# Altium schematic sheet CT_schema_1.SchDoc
size 542 x 258 mm
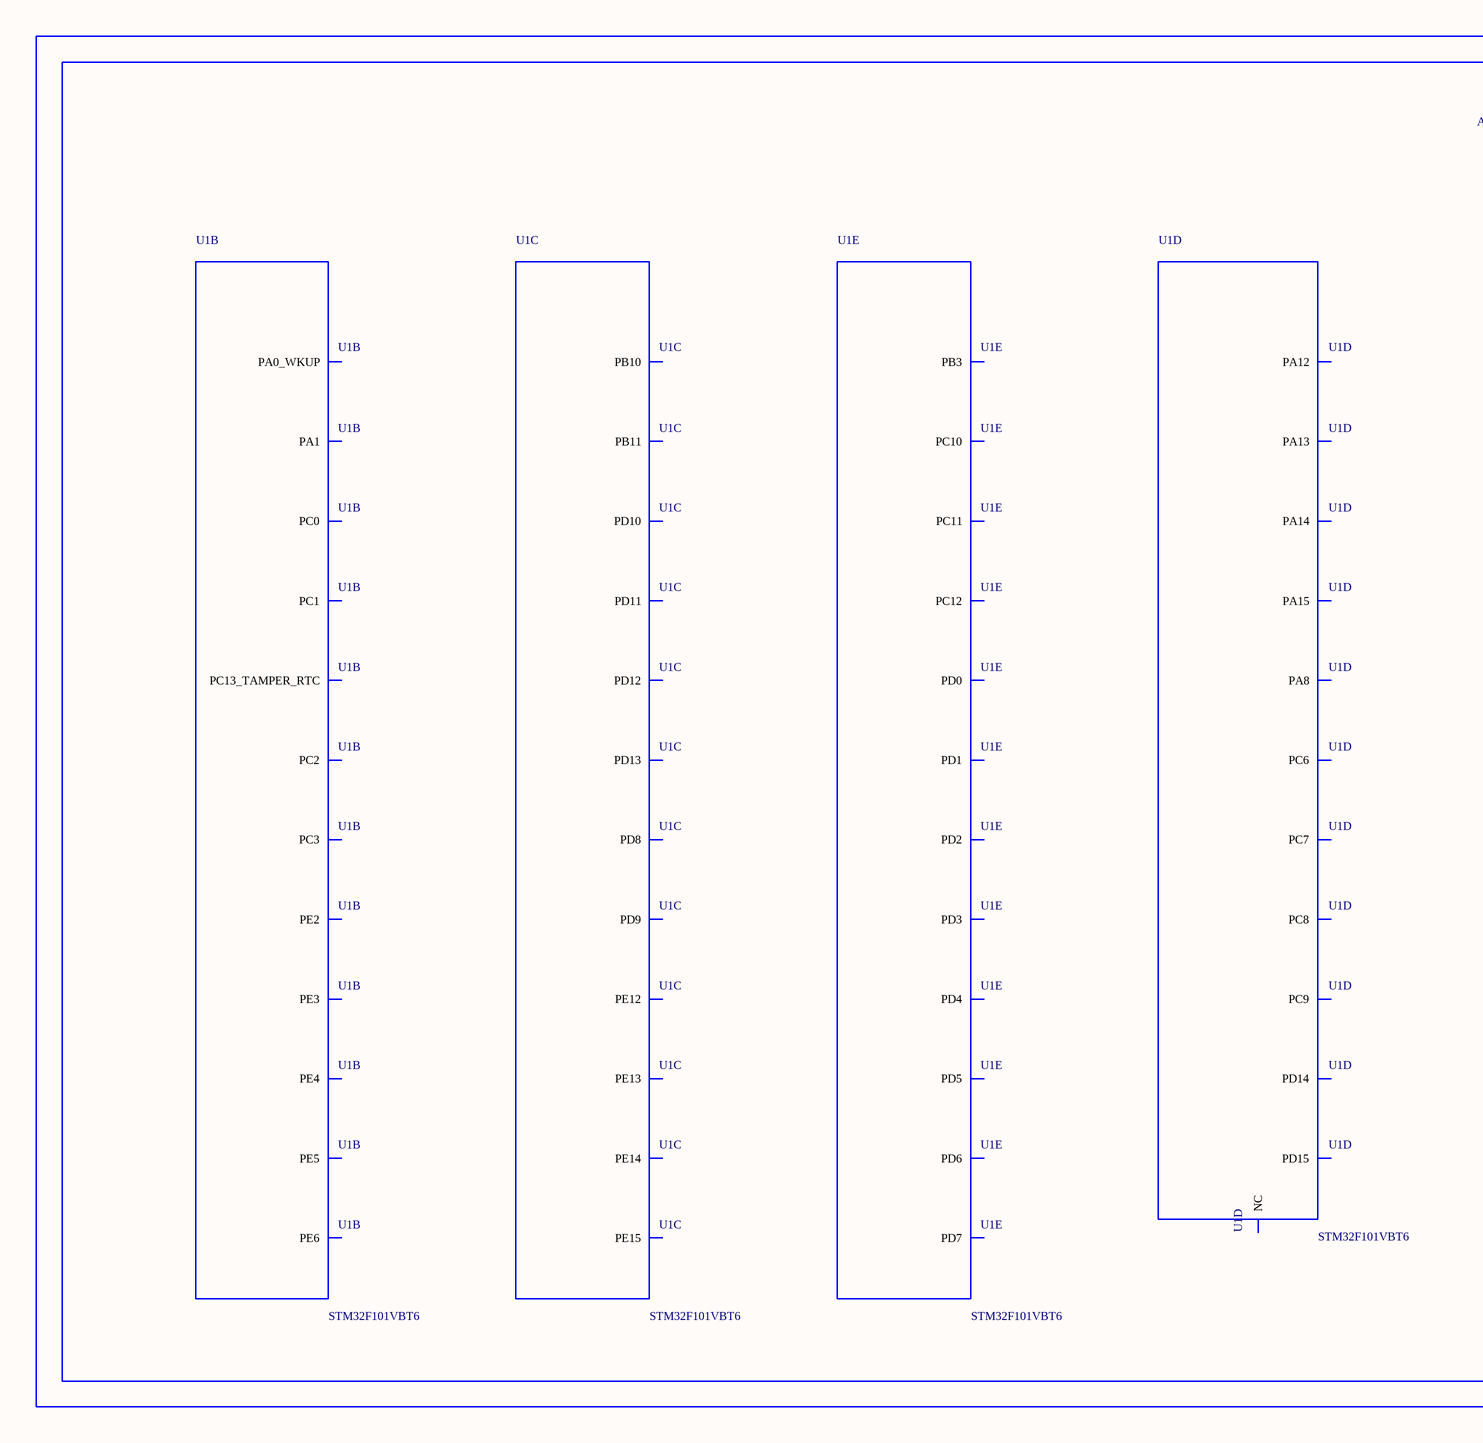
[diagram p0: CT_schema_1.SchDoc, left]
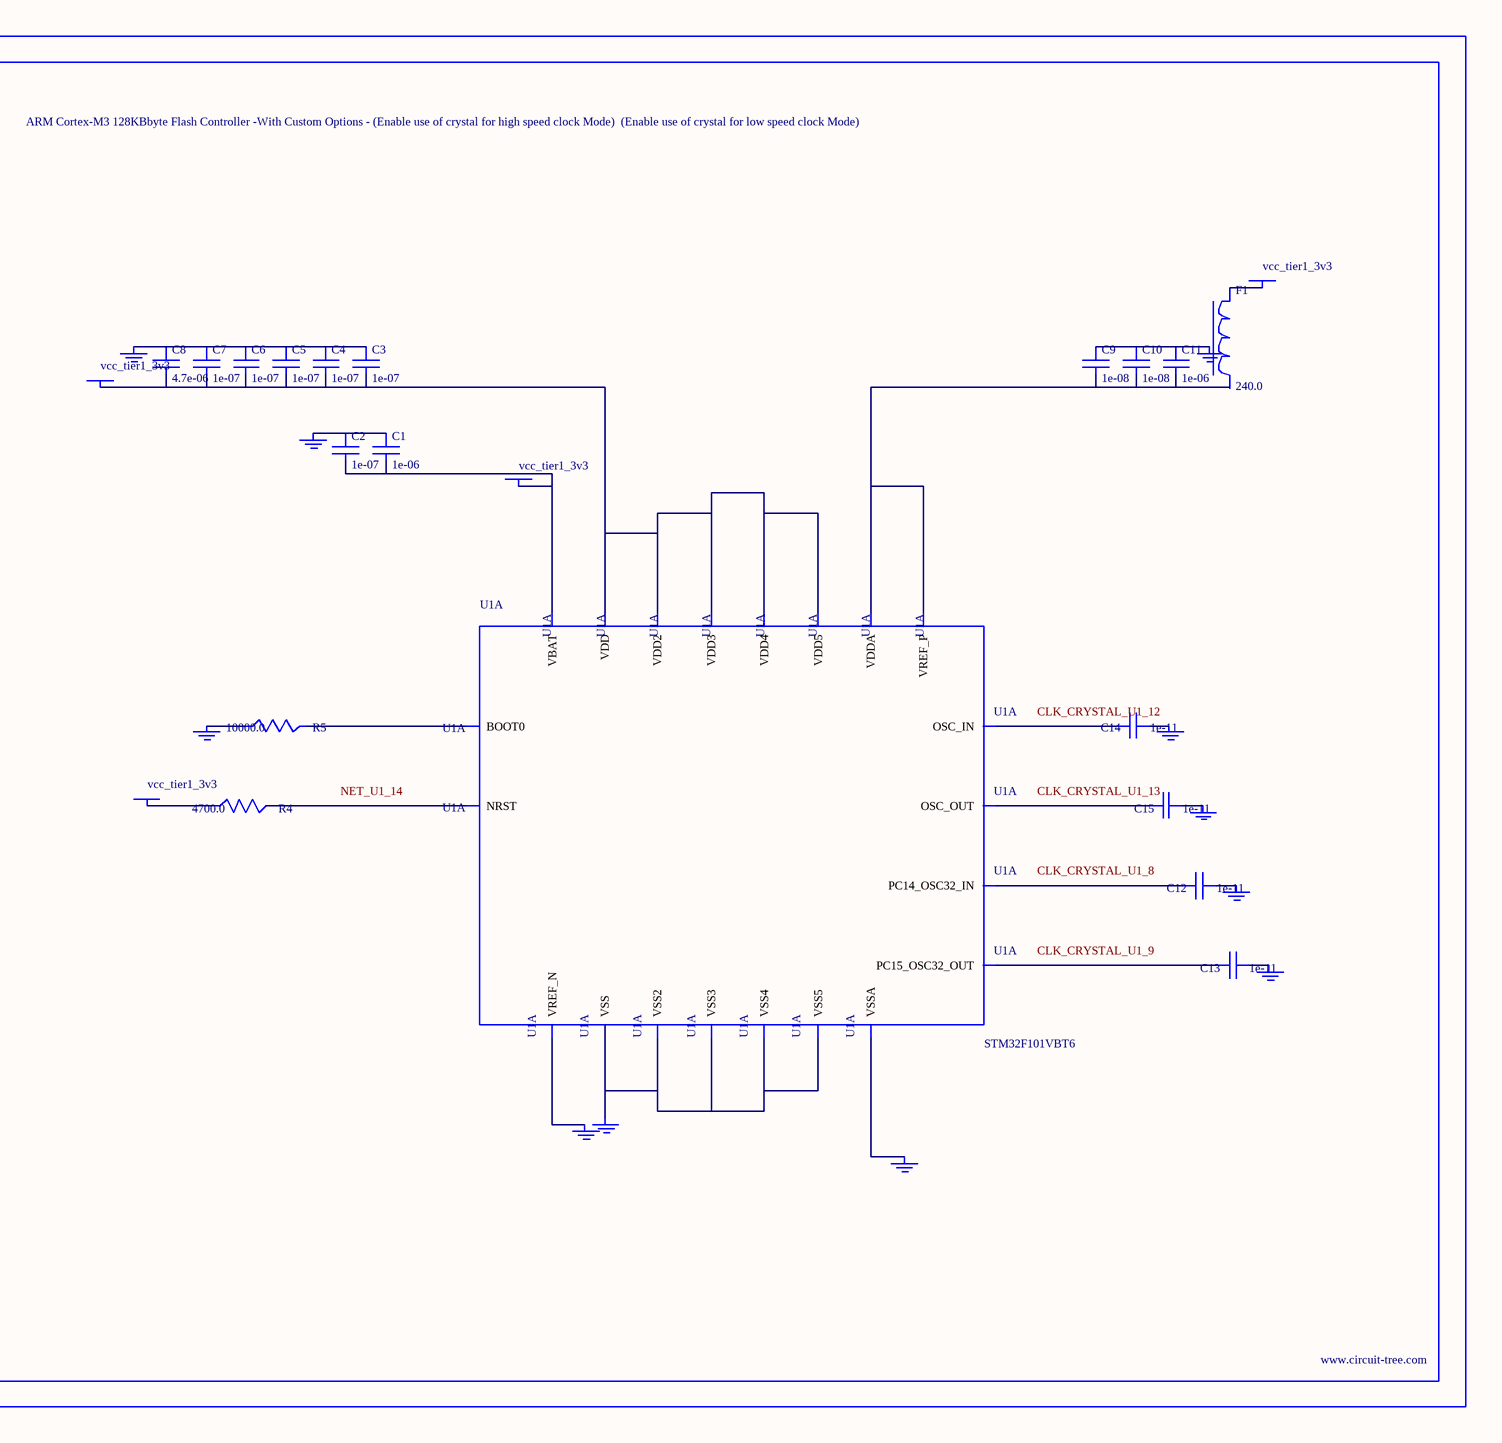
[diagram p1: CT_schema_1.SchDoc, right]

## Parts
BORDER0  (no value)
C1  1e-06  [C0603]
C2  1e-07  [C0603]
C3  1e-07  [C0603]
C4  1e-07  [C0603]
C5  1e-07  [C0603]
C6  1e-07  [C0603]
C7  1e-07  [C0603]
C8  4.7e-06  [C0603]
C9  1e-08  [C0603]
C10  1e-08  [C0603]
C11  1e-06  [C0603]
C12  1e-11  [C0402]
C13  1e-11  [C0402]
C14  1e-11  [C0402]
C15  1e-11  [C0402]
F1  240.0  [L0603]
GND_INSTANCE_0_0  (no value)
GND_INSTANCE_0_1  (no value)
GND_INSTANCE_0_2  (no value)
GND_INSTANCE_0_3  (no value)
GND_INSTANCE_0_4  (no value)
GND_INSTANCE_0_5  (no value)
GND_INSTANCE_0_6  (no value)
GND_INSTANCE_0_7  (no value)
GND_INSTANCE_0_8  (no value)
GND_INSTANCE_0_9  (no value)
GND_INSTANCE_0_10  (no value)
POWER_INSTANCE_0_0  vcc_tier1_3v3
POWER_INSTANCE_0_1  vcc_tier1_3v3
POWER_INSTANCE_0_2  vcc_tier1_3v3
POWER_INSTANCE_0_3  vcc_tier1_3v3
R4  4700.0  [R0603]
R5  10000.0  [R0603]
U1  STM32F101VBT6  [LQFP100]  (parts A,B,C,D,E of 9)

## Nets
NetC1_1: C1.1 C2.1 GND_INSTANCE_0_0.0(GND)
NetC1_2: C1.2 C2.2 POWER_INSTANCE_0_0.0(PWR) U1.6(VBAT)
NetC3_1: C3.1 C4.1 C5.1 C6.1 C7.1 C8.1 GND_INSTANCE_0_3.0(GND)
NetC3_2: C3.2 C4.2 C5.2 C6.2 C7.2 C8.2 POWER_INSTANCE_0_1.0(PWR) U1.11(VDD) U1.28(VDD2) U1.50(VDD3) U1.75(VDD4) U1.100(VDD5)
NetC9_1: C9.1 C10.1 C11.1 GND_INSTANCE_0_8.0(GND)
NetC9_2: C9.2 C10.2 C11.2 U1.21(VREF_P) U1.22(VDDA)
NetC12_1: C12.1 GND_INSTANCE_0_1.0(GND)
NetC12_2: C12.2 U1.8(PC14_OSC32_IN)
NetC13_1: C13.1 GND_INSTANCE_0_2.0(GND)
NetC13_2: C13.2 U1.9(PC15_OSC32_OUT)
NetC14_1: C14.1 GND_INSTANCE_0_4.0(GND)
NetC14_2: C14.2 U1.12(OSC_IN)
NetC15_1: C15.1 GND_INSTANCE_0_5.0(GND)
NetC15_2: C15.2 U1.13(OSC_OUT)
NetF1_1: F1.1 POWER_INSTANCE_0_2.0(PWR)
NetGND_INSTANCE_0_6_0: GND_INSTANCE_0_6.0(GND) U1.19(VSSA)
NetGND_INSTANCE_0_7_0: GND_INSTANCE_0_7.0(GND) U1.20(VREF_N)
NetGND_INSTANCE_0_9_0: GND_INSTANCE_0_9.0(GND) R5.1
NetGND_INSTANCE_0_10_0: GND_INSTANCE_0_10.0(GND) U1.10(VSS) U1.27(VSS2) U1.49(VSS3) U1.74(VSS4) U1.99(VSS5)
NetPOWER_INSTANCE_0_3_0: POWER_INSTANCE_0_3.0(PWR) R4.1
NetR4_2: R4.2 U1.14(NRST)
NetR5_2: R5.2 U1.94(BOOT0)

Not connected (* = marked no-connect by the designer): F1 2; U1 1(PE2) 2(PE3) 3(PE4) 4(PE5) 5(PE6) 7(PC13_TAMPER_RTC) 15(PC0) 16(PC1) 17(PC2) 18(PC3) 23(PA0_WKUP) 24(PA1) 43(PE12) 44(PE13) 45(PE14) 46(PE15) 47(PB10) 48(PB11) 55(PD8) 56(PD9) 57(PD10) 58(PD11) 59(PD12) 60(PD13) 61(PD14) 62(PD15) 63(PC6) 64(PC7) 65(PC8) 66(PC9) 67(PA8) 71(PA12) 72(PA13) 73(NC) 76(PA14) 77(PA15) 78(PC10) 79(PC11) 80(PC12) 81(PD0) 82(PD1) 83(PD2) 84(PD3) 85(PD4) 86(PD5) 87(PD6) 88(PD7) 89(PB3)

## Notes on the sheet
- Labels drawn without touching a wire or pin: CLK_CRYSTAL_U1_8, CLK_CRYSTAL_U1_9, CLK_CRYSTAL_U1_12, CLK_CRYSTAL_U1_13, NET_U1_14

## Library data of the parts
BORDER0 = BORDER_PAGE0
C1 C11 = C0603C105K3RACTU
C2-C7 = 06035C104K4Z2A
C8 = GRM188R6YA475KE15D
C9 C10 = 06035C103K4Z2A
C12-C15 = C0402C100K3GACTU
F1 = Z0603C241ASMST
GND_INSTANCE_0_0-GND_INSTANCE_0_10 = GND
POWER_INSTANCE_0_0-POWER_INSTANCE_0_3 = PWR
R4 = RC0603JR-074K7L
R5 = RC0603JR-0710KL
